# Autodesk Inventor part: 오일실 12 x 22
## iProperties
IsCustomPart: 0
Created: 2015-10
Part Number: 오일실 12 x 22
Material: 고무
Description: 오일-실
Document SubType Name: Modeling
Standard: KS B 2804
Designer: mdu
Standards Organization: KS
Language: ko-KR
Size Designation: S - 12 22 7
Categories: <MemberInstance><Categories><Category DisplayName="샤프트 부품" InternalName="7f7aeb1f-a693-4053-b835-cee3144e0d98" Mnemonic="SHFT"><Category DisplayName="실링" Intern
Density: 0.93 g/cm^3
Author: mdu
